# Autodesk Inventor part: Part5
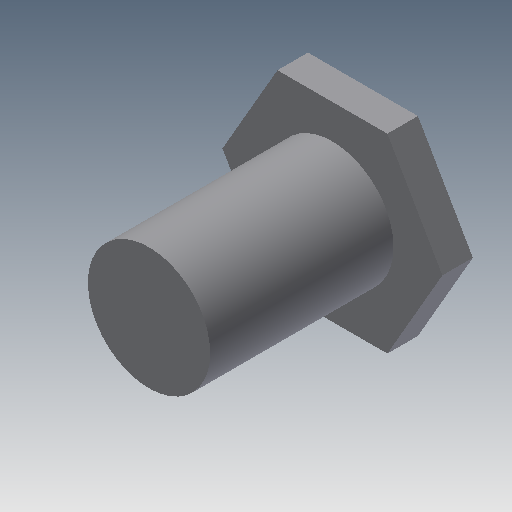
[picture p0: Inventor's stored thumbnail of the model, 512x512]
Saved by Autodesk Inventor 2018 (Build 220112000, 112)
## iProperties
Created: 2008-05
Part Number: Part5
Document SubType Name: Modeling
Designer: CADCIM
Density: 1 g/cm^3
Material: Generic
Appearance: Default
Author: CADCIM
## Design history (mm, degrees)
sketch "Sketch1"
  geometry: C1 r 2 at (-7.12, 11.618)
  constraints: 1 centre point
  dimensions: "d2" = 4 diameter of C1
extrude "Extrusion1" new body sketch "Sketch1" distance "d0" = 6; taper "d1" = 0 deg
sketch "Sketch2"
  geometry: L1 (-3.598, 0)-(-1.799, 3.116); L2 (-1.799, 3.116)-(1.799, 3.116); L3 (1.799, 3.116)-(3.598, 0); L4 (3.598, 0)-(1.799, -3.116); L5 (1.799, -3.116)-(-1.799, -3.116); L6 (-1.799, -3.116)-(-3.598, 0); C1 r 2 at (0, 0) reference; 1 further point
  constraints: 12 end point, 1 coincident, 13 other
extrude "Extrusion2" join sketch "Sketch2" distance "d3" = 1; taper "d4" = 0 deg
body "Solid1"
